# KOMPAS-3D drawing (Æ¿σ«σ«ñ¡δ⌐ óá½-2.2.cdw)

Views: Вид 1, Вид 2, Вид 3
Referenced files: Тихоходный вал.cdw
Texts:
  Тихоходный вал
  Беляев Андрей Константинович
  Noncommercial version
  Ra 1,6
  Ra 3,2
  Ra 2,5
  Термообработка посадочных мест - закалка с последующим
  отпуском.
  * Размер для справок.
  Rz 20
  Тихоходный
  вал
  Сталь 45 ГОСТ 1050-88
Dimensions and other numbers on the sheet: 605; 60; 30; 96; 44; 165; 88; 26; 2,5; 5 фасок; 110; 125; 130; 80; 150; 90; 2; 4; 2 скруг.; 8; 109; 71; 119; 32; 99; 1:2,5; 1; 45; 0; 3; 5; 6; 7; 9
